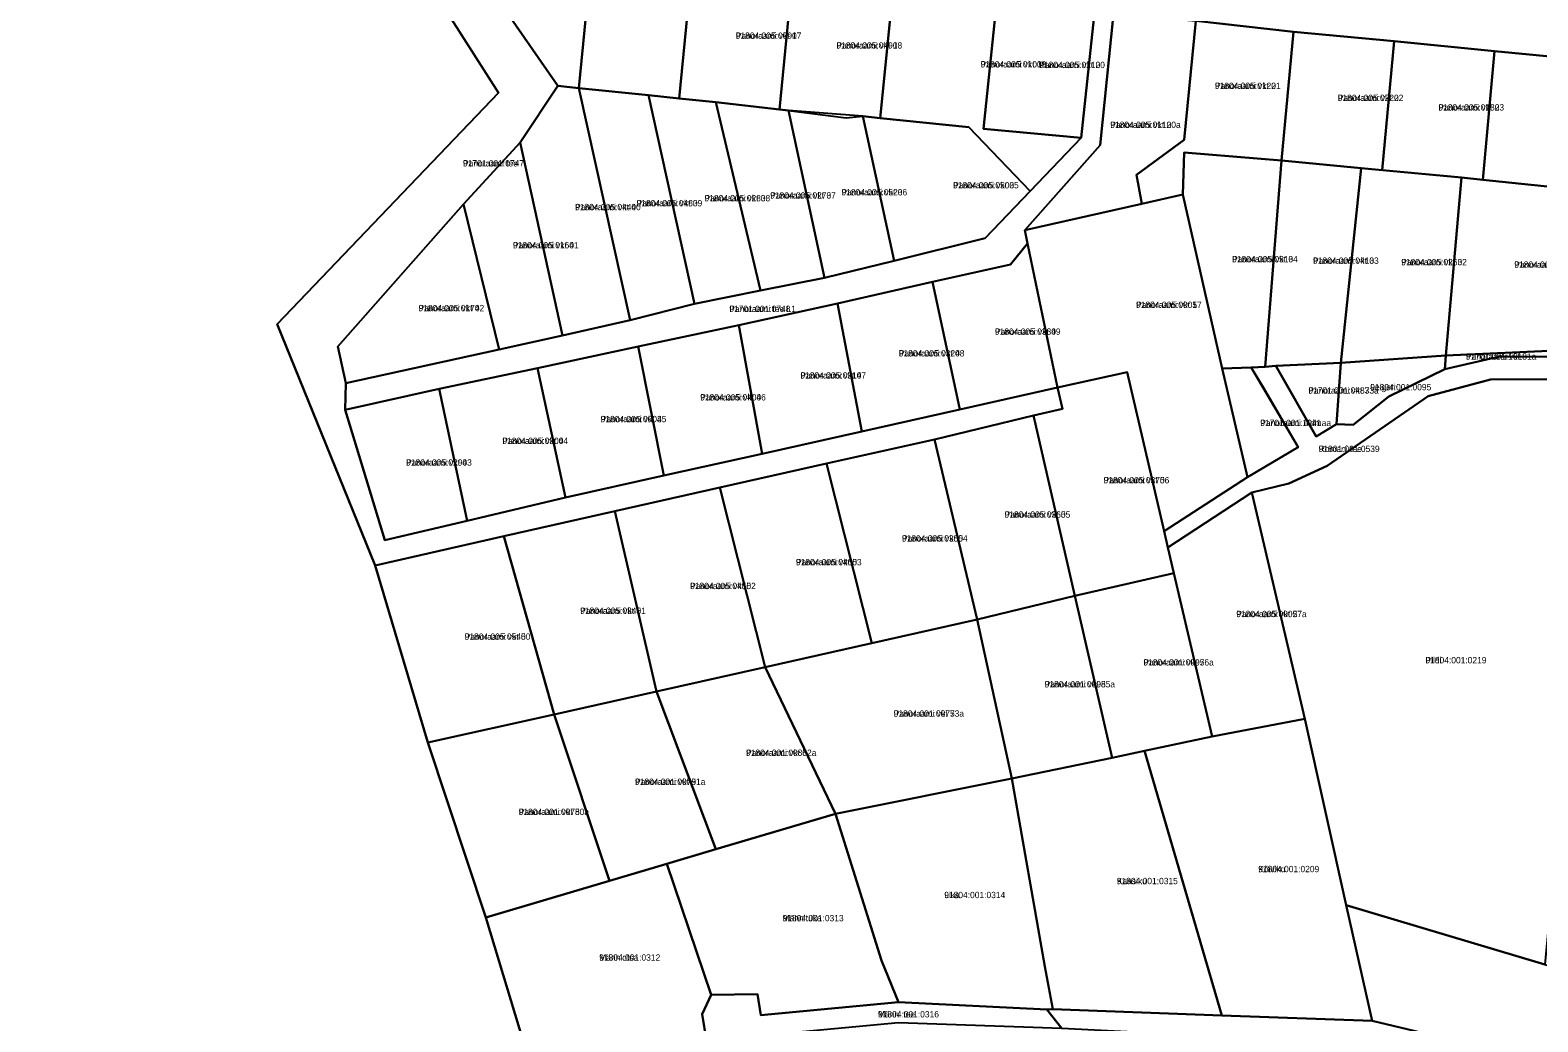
# Model space of a CAD drawing. Extents: x 655954 to 711923, y 6395079 to 6429745.
# Drawn here: x 676838.5 to 677196.9, y 6413488.9 to 6413724.6 of the extents above; entities that cross this region are included whole.
import ezdxf

# ---------------------------------------------------------------- set-up
doc = ezdxf.new("R2010")
doc.units = 0
for name, color, linetype in [('L_AADRESS', 7, 'Continuous'), ('PIIR', 7, 'Continuous'), ('TUNNUS', 7, 'Continuous')]:
    doc.layers.add(name, color=color, linetype=linetype)

msp = doc.modelspace()

# ---------------------------------------------------------------- linework, layer by layer
at = {"layer": 'PIIR'}
for points in [[(676722.83, 6413814.18), (676900.55, 6413787.01), (676949.83, 6413709.71), (676897.23, 6413654.7), (676920.56, 6413597.36), (676933.05, 6413555.27), (676946.82, 6413513.73), (676956.91, 6413480.43), (677002.62, 6413329.06), (677066.33, 6413319.15), (677231.27, 6413342.1), (677307.23, 6413354.1), (677309.72, 6413343.84), (677384.24, 6413366.61), (677380.25, 6413324.84), (677459.83, 6413354.2), (677597.5, 6413335.31), (677731.86, 6413311.49), (678085.04, 6413297.98), (678099.28, 6413215.93), (678143.84, 6412925.74)], [(676940.74, 6413744.84), (676963.98, 6413711.35), (676955.01, 6413697.89), (676941.57, 6413683.21), (676911.65, 6413649.44), (676913.57, 6413640.66), (676913.44, 6413634.36), (676922.88, 6413603.4), (676942.38, 6413608.01), (676965.79, 6413613.5), (676989.16, 6413618.75), (677012.51, 6413623.89), (677036.26, 6413629.17), (677059.56, 6413634.44), (677082.73, 6413639.64), (677083.95, 6413634.6), (677077.02, 6413633.03), (677053.51, 6413627.34), (677027.86, 6413621.6), (677002.51, 6413615.89), (676977.55, 6413610.28), (676951.13, 6413604.32), (676920.56, 6413597.36), (676897.23, 6413654.7), (676949.83, 6413709.71), (676900.55, 6413787.01)], [(677210.51, 6413717.3), (677186.62, 6413719.58), (677162.73, 6413721.93), (677138.84, 6413724.17), (677115.64, 6413726.84)], [(677204.22, 6413641.61), (677185.64, 6413641.55), (677170.88, 6413637.64), (677146.87, 6413621.01), (677137.72, 6413616.82), (677128.9, 6413614.75), (677108.98, 6413601.65), (677108.09, 6413605.56), (677127.88, 6413618.37), (677139.96, 6413625.52), (677128.81, 6413644.41), (677132.06, 6413644.54), (677134.66, 6413644.84), (677144.2, 6413628.03), (677149.07, 6413630.93), (677152.98, 6413630.76), (677161.51, 6413637.51), (677174.78, 6413644.05), (677187.89, 6413647.01), (677203.04, 6413646.92)]]:
    msp.add_lwpolyline(points, dxfattribs=at)
for points in [[(676963.98, 6413711.35), (676940.74, 6413744.84), (676971.97, 6413741.71), (676968.95, 6413710.82)], [(676968.95, 6413710.82), (676971.97, 6413741.71), (676995.85, 6413739.2), (676992.82, 6413708.35), (676985.56, 6413709.1)], [(676995.85, 6413739.2), (677019.7, 6413736.8), (677016.69, 6413705.72), (677001.51, 6413707.46), (676992.82, 6413708.35)], [(677040.59, 6413703.7), (677036.44, 6413704.17), (677018.82, 6413705.46), (677016.69, 6413705.72), (677019.7, 6413736.8), (677043.7, 6413734.54)], [(677043.7, 6413734.54), (677068.41, 6413732.49), (677065.16, 6413701.16), (677088.34, 6413698.99), (677076.26, 6413686.33), (677061.68, 6413701.52), (677040.59, 6413703.7)], [(677068.41, 6413732.49), (677091.65, 6413729.52), (677088.34, 6413698.99), (677065.16, 6413701.16)], [(677096.04, 6413728.43), (677092.88, 6413697.28), (677074.94, 6413677.09), (677075.6, 6413673.91), (677071.54, 6413668.9), (677053, 6413664.75), (677030.45, 6413659.62), (677007.01, 6413654.46), (676983.1, 6413649.39), (676959.15, 6413644.23), (676935.79, 6413639.38), (676913.44, 6413634.36), (676913.57, 6413640.66), (676950.06, 6413648.7), (676965.05, 6413651.99), (676981.14, 6413655.65), (676996.43, 6413659.58), (677012.12, 6413662.7), (677027.37, 6413665.74), (677043.95, 6413669.78), (677065.56, 6413675.12), (677076.26, 6413686.33), (677088.34, 6413698.99), (677091.65, 6413729.52)], [(677092.88, 6413697.28), (677096.04, 6413728.43), (677115.64, 6413726.84), (677112.86, 6413698.56), (677101.48, 6413690.21), (677102.75, 6413683.33), (677074.94, 6413677.09)], [(677112.88, 6413695.51), (677112.51, 6413685.52), (677102.75, 6413683.33), (677101.48, 6413690.21), (677112.86, 6413698.56), (677115.64, 6413726.84), (677138.84, 6413724.17), (677135.97, 6413693.58)], [(677135.97, 6413693.58), (677138.84, 6413724.17), (677162.73, 6413721.93), (677159.94, 6413691.32), (677154.89, 6413691.79)], [(677178.79, 6413689.57), (677159.94, 6413691.32), (677162.73, 6413721.93), (677186.62, 6413719.58), (677183.86, 6413689.04)], [(677207.63, 6413686.54), (677183.86, 6413689.04), (677186.62, 6413719.58), (677210.51, 6413717.3)], [(676955.01, 6413697.89), (676963.98, 6413711.35), (676968.95, 6413710.82), (676981.14, 6413655.65), (676965.05, 6413651.99)], [(676968.95, 6413710.82), (676985.56, 6413709.1), (676996.43, 6413659.58), (676981.14, 6413655.65)], [(676985.56, 6413709.1), (676992.82, 6413708.35), (677001.51, 6413707.46), (677012.12, 6413662.7), (676996.43, 6413659.58)], [(677012.12, 6413662.7), (677001.51, 6413707.46), (677016.69, 6413705.72), (677018.82, 6413705.46), (677027.37, 6413665.74)], [(677032.51, 6413703.76), (677036.44, 6413704.17), (677043.95, 6413669.78), (677027.37, 6413665.74), (677018.82, 6413705.46)], [(677043.95, 6413669.78), (677036.44, 6413704.17), (677040.59, 6413703.7), (677061.68, 6413701.52), (677076.26, 6413686.33), (677065.56, 6413675.12)], [(676950.06, 6413648.7), (676941.57, 6413683.21), (676955.01, 6413697.89), (676965.05, 6413651.99)], [(677132.06, 6413644.54), (677128.81, 6413644.41), (677121.89, 6413644.18), (677112.51, 6413685.52), (677112.88, 6413695.51), (677135.97, 6413693.58)], [(677154.89, 6413691.79), (677150.08, 6413645.55), (677134.66, 6413644.84), (677132.06, 6413644.54), (677135.97, 6413693.58)], [(677154.89, 6413691.79), (677178.79, 6413689.57), (677175.01, 6413647.24), (677150.08, 6413645.55)], [(677178.79, 6413689.57), (677183.86, 6413689.04), (677207.63, 6413686.54), (677203.2, 6413648.53), (677175.01, 6413647.24)], [(676913.57, 6413640.66), (676911.65, 6413649.44), (676941.57, 6413683.21), (676950.06, 6413648.7)], [(677112.51, 6413685.52), (677121.89, 6413644.18), (677127.88, 6413618.37), (677108.09, 6413605.56), (677099.27, 6413643.29), (677082.73, 6413639.64), (677075.6, 6413673.91), (677074.94, 6413677.09), (677102.75, 6413683.33)], [(677059.56, 6413634.44), (677053, 6413664.75), (677071.54, 6413668.9), (677075.6, 6413673.91), (677082.73, 6413639.64)], [(677059.56, 6413634.44), (677036.26, 6413629.17), (677030.45, 6413659.62), (677053, 6413664.75)], [(677036.26, 6413629.17), (677012.51, 6413623.89), (677007.01, 6413654.46), (677030.45, 6413659.62)], [(677012.51, 6413623.89), (676989.16, 6413618.75), (676983.1, 6413649.39), (677007.01, 6413654.46)], [(676965.79, 6413613.5), (676959.15, 6413644.23), (676983.1, 6413649.39), (676989.16, 6413618.75)], [(677149.07, 6413630.93), (677150.08, 6413645.55), (677175.01, 6413647.24), (677174.78, 6413644.05), (677161.51, 6413637.51), (677152.98, 6413630.76)], [(677187.89, 6413647.01), (677174.78, 6413644.05), (677175.01, 6413647.24), (677203.2, 6413648.53), (677203.04, 6413646.92)], [(676942.38, 6413608.01), (676935.79, 6413639.38), (676959.15, 6413644.23), (676965.79, 6413613.5)], [(677099.27, 6413643.29), (677108.09, 6413605.56), (677108.98, 6413601.65), (677110.38, 6413595.57), (677086.82, 6413590.14), (677077.02, 6413633.03), (677083.95, 6413634.6), (677082.73, 6413639.64)], [(677139.96, 6413625.52), (677127.88, 6413618.37), (677121.89, 6413644.18), (677128.81, 6413644.41), (677131.35, 6413640.1)], [(677144.2, 6413628.03), (677134.66, 6413644.84), (677150.08, 6413645.55), (677149.07, 6413630.93)], [(676913.44, 6413634.36), (676935.79, 6413639.38), (676942.38, 6413608.01), (676922.88, 6413603.4)], [(677128.9, 6413614.75), (677137.72, 6413616.82), (677146.87, 6413621.01), (677170.88, 6413637.64), (677185.64, 6413641.55), (677204.22, 6413641.61), (677211.49, 6413638.78), (677198.6, 6413502.57), (677151.34, 6413516.67), (677141.49, 6413560.95)], [(677063.67, 6413584.52), (677053.51, 6413627.34), (677077.02, 6413633.03), (677086.82, 6413590.14)], [(677038.64, 6413578.92), (677027.86, 6413621.6), (677053.51, 6413627.34), (677063.67, 6413584.52)], [(677013.27, 6413573.23), (677002.51, 6413615.89), (677027.86, 6413621.6), (677038.64, 6413578.92)], [(677013.27, 6413573.23), (676987.43, 6413567.4), (676977.55, 6413610.28), (677002.51, 6413615.89)], [(677128.9, 6413614.75), (677141.49, 6413560.95), (677119.5, 6413556.75), (677110.38, 6413595.57), (677108.98, 6413601.65)], [(676987.43, 6413567.4), (676963.1, 6413561.94), (676951.13, 6413604.32), (676977.55, 6413610.28)], [(676963.1, 6413561.94), (676933.05, 6413555.27), (676920.56, 6413597.36), (676951.13, 6413604.32)], [(677086.82, 6413590.14), (677110.38, 6413595.57), (677119.5, 6413556.75), (677103.38, 6413553.34), (677095.71, 6413551.68)], [(677086.82, 6413590.14), (677095.71, 6413551.68), (677071.85, 6413546.76), (677063.67, 6413584.52)], [(677063.67, 6413584.52), (677071.85, 6413546.76), (677030, 6413538.34), (677013.27, 6413573.23), (677038.64, 6413578.92)], [(677013.27, 6413573.23), (677030, 6413538.34), (677001.53, 6413529.92), (676987.43, 6413567.4)], [(676987.43, 6413567.4), (677001.53, 6413529.92), (676989.89, 6413526.46), (676976.29, 6413522.42), (676963.1, 6413561.94)], [(676963.1, 6413561.94), (676976.29, 6413522.42), (676946.82, 6413513.73), (676933.05, 6413555.27)], [(677103.38, 6413553.34), (677119.5, 6413556.75), (677141.49, 6413560.95), (677151.34, 6413516.67), (677157.51, 6413489.18), (677121.82, 6413490.43)], [(677071.85, 6413546.76), (677095.71, 6413551.68), (677103.38, 6413553.34), (677121.82, 6413490.43), (677081.65, 6413491.89), (677079.74, 6413502.08)], [(677030, 6413538.34), (677071.85, 6413546.76), (677079.74, 6413502.08), (677081.65, 6413491.89), (677080.22, 6413491.88), (677044.94, 6413493.61), (677040.88, 6413503.53)], [(676989.89, 6413526.46), (677001.53, 6413529.92), (677030, 6413538.34), (677040.88, 6413503.53), (677044.94, 6413493.61), (677012.26, 6413490.53), (677011.41, 6413495.5), (677000.44, 6413495.3)], [(677332.5, 6413536.88), (677338.79, 6413525.55), (677342.28, 6413516.7), (677349.03, 6413493.33), (677350.52, 6413489.54), (677337.82, 6413480.42), (677317.74, 6413472.95), (677288.46, 6413465.7), (677285.56, 6413465.3), (677276.11, 6413465.46), (677252.03, 6413468.89), (677204.37, 6413479.13), (677189.8, 6413481.47), (677157.51, 6413489.18), (677151.34, 6413516.67), (677198.6, 6413502.57), (677231.99, 6413492.6), (677272.8, 6413510.64)], [(676946.82, 6413513.73), (676976.29, 6413522.42), (676989.89, 6413526.46), (677000.44, 6413495.3), (676998.27, 6413490.74), (676999.3, 6413484.43), (676956.91, 6413480.43)], [(677000.44, 6413495.3), (677011.41, 6413495.5), (677012.26, 6413490.53), (677044.94, 6413493.61), (677080.22, 6413491.88), (677083.78, 6413487.37), (677044.94, 6413488.65), (676999.3, 6413484.43), (676998.27, 6413490.74)], [(677083.78, 6413487.37), (677080.22, 6413491.88), (677081.65, 6413491.89), (677121.82, 6413490.43), (677157.51, 6413489.18), (677189.8, 6413481.47), (677204.37, 6413479.13), (677252.03, 6413468.89), (677276.11, 6413465.46), (677285.56, 6413465.3), (677288.46, 6413465.7), (677317.74, 6413472.95), (677337.82, 6413480.42), (677350.52, 6413489.54), (677353.31, 6413480.81), (677291.42, 6413461.29), (677284.13, 6413460.03), (677272.97, 6413460.6), (677231.21, 6413468.51), (677155.12, 6413483.7)]]:
    msp.add_lwpolyline(points, close=True, dxfattribs=at)

# ---------------------------------------------------------------- texts
at = {"layer": 'L_AADRESS'}
for s, p in [('Panoraami vkt 17', (677006.26, 6413722.53)), ('Panoraami vkt 18', (677030.2, 6413720.22)), ('Panoraami vkt 19', (677064.47, 6413715.72)), ('Panoraami vkt 20', (677078.4, 6413715.57)), ('Panoraami vkt 21', (677120.16, 6413710.61)), ('Panoraami vkt 22', (677149.35, 6413707.75)), ('Panoraami vkt 23', (677173.28, 6413705.49)), ('Panoraami vkt 20a', (677095.29, 6413701.35)), ('Panoraami tee', (676941.43, 6413692.19)), ('Panoraami vkt 37', (677014.44, 6413684.57)), ('Panoraami vkt 36', (677031.39, 6413685.31)), ('Panoraami vkt 35', (677057.92, 6413686.98)), ('Panoraami vkt 40', (676968.07, 6413681.8)), ('Panoraami vkt 39', (676982.69, 6413682.72)), ('Panoraami vkt 38', (676998.84, 6413683.9)), ('Panoraami vkt 41', (676953.31, 6413672.72)), ('Panoraami vkt 34', (677124.24, 6413669.41)), ('Panoraami vkt 33', (677143.48, 6413669.06)), ('Panoraami vkt 32', (677164.43, 6413668.71)), ('Panoraami vkt 31', (677191.32, 6413668.12)), ('Panoraami vkt 42', (676930.86, 6413657.79)), ('Panoraami tee L1', (677004.74, 6413657.61)), ('Panoraami vkt 57', (677101.41, 6413658.58)), ('Panoraami vkt 49', (677067.86, 6413652.19)), ('Panoraami vkt 48', (677045.01, 6413647.04)), ('Panoraami vkt 31a', (677179.82, 6413646.29)), ('Panoraami vkt 47', (677021.63, 6413641.8)), ('Panoraami vkt 33a', (677142.37, 6413638.22)), ('Leigeri', (677157.08, 6413639)), ('Panoraami vkt 46', (676997.8, 6413636.58)), ('Panoraami vkt 45', (676974.15, 6413631.42)), ('Panoraami üldmaa', (677130.93, 6413630.5)), ('Panoraami vkt 44', (676950.79, 6413626.24)), ('Romani tee', (677144.81, 6413624.33)), ('Panoraami vkt 43', (676927.91, 6413621.1)), ('Panoraami vkt 56', (677093.7, 6413616.89)), ('Panoraami vkt 55', (677070.16, 6413608.73)), ('Panoraami vkt 54', (677045.77, 6413603.06)), ('Panoraami vkt 53', (677020.57, 6413597.41)), ('Panoraami vkt 52', (676995.41, 6413591.75)), ('Panoraami vkt 51', (676969.28, 6413585.87)), ('Panoraami vkt 57a', (677125.23, 6413585.09)), ('Panoraami vkt 50', (676941.83, 6413579.71)), ('Panoraami vkt 56a', (677103.16, 6413573.6)), ('Pildi', (677170.2, 6413574.11)), ('Panoraami vkt 55a', (677079.69, 6413568.39)), ('Panoraami vkt 53a', (677043.8, 6413561.43)), ('Panoraami vkt 52a', (677008.71, 6413552.12)), ('Panoraami vkt 51a', (676982.32, 6413545.23)), ('Panoraami vkt 50a', (676954.67, 6413538.06)), ('Kõiviku', (677130.45, 6413524.48)), ('Kaasiku', (677096.84, 6413521.63)), ('Lika', (677055.82, 6413518.31)), ('Männituka', (677017.41, 6413512.82)), ('Männiotsa', (676973.81, 6413503.45)), ('Männi tee', (677040.06, 6413489.96))]:
    msp.add_text(s, height=1.5, dxfattribs=at).set_placement(p)
at = {"layer": 'TUNNUS'}
for s, p in [('91804:005:0090', (677006.26, 6413722.53)), ('91804:005:0490', (677030.2, 6413720.22)), ('91804:005:0100', (677064.47, 6413715.72)), ('91804:005:0210', (677078.4, 6413715.57)), ('91804:005:0120', (677120.16, 6413710.61)), ('91804:005:0220', (677149.35, 6413707.75)), ('91804:005:0130', (677173.28, 6413705.49)), ('91804:005:0110', (677095.29, 6413701.35)), ('91701:001:0747', (676941.43, 6413692.19)), ('91804:005:0270', (677014.44, 6413684.57)), ('91804:005:0520', (677031.39, 6413685.31)), ('91804:005:0500', (677057.92, 6413686.98)), ('91804:005:0440', (676968.07, 6413681.8)), ('91804:005:0480', (676982.69, 6413682.72)), ('91804:005:0280', (676998.84, 6413683.9)), ('91804:005:0160', (676953.31, 6413672.72)), ('91804:005:0510', (677124.24, 6413669.41)), ('91804:005:0410', (677143.48, 6413669.06)), ('91804:005:0260', (677164.43, 6413668.71)), ('91804:005:0390', (677191.32, 6413668.12)), ('91804:005:0170', (676930.86, 6413657.79)), ('91701:001:0748', (677004.74, 6413657.61)), ('91804:005:0001', (677101.41, 6413658.58)), ('91804:005:0330', (677067.86, 6413652.19)), ('91804:005:0320', (677045.01, 6413647.04)), ('91701:001:1618', (677179.82, 6413646.29)), ('91804:005:0310', (677021.63, 6413641.8)), ('91701:001:0487', (677142.37, 6413638.22)), ('91804:001:0095', (677157.08, 6413639)), ('91804:005:0400', (676997.8, 6413636.58)), ('91804:005:0003', (676974.15, 6413631.42)), ('91701:001:1041', (677130.93, 6413630.5)), ('91804:005:0300', (676950.79, 6413626.24)), ('91801:001:0539', (677144.81, 6413624.33)), ('91804:005:0290', (676927.91, 6413621.1)), ('91804:005:0370', (677093.7, 6413616.89)), ('91804:005:0360', (677070.16, 6413608.73)), ('91804:005:0350', (677045.77, 6413603.06)), ('91804:005:0460', (677020.57, 6413597.41)), ('91804:005:0450', (676995.41, 6413591.75)), ('91804:005:0340', (676969.28, 6413585.87)), ('91804:005:0002', (677125.23, 6413585.09)), ('91804:005:0540', (676941.83, 6413579.71)), ('91804:001:0097', (677103.16, 6413573.6)), ('91804:001:0219', (677170.2, 6413574.11)), ('91804:001:0098', (677079.69, 6413568.39)), ('91804:001:0077', (677043.8, 6413561.43)), ('91804:001:0080', (677008.71, 6413552.12)), ('91804:001:0079', (676982.32, 6413545.23)), ('91804:001:0078', (676954.67, 6413538.06)), ('91804:001:0209', (677130.45, 6413524.48)), ('91804:001:0315', (677096.84, 6413521.63)), ('91804:001:0314', (677055.82, 6413518.31)), ('91804:001:0313', (677017.41, 6413512.82)), ('91804:001:0312', (676973.81, 6413503.45)), ('91804:001:0316', (677040.06, 6413489.96))]:
    msp.add_text(s, height=1.5, dxfattribs=at).set_placement(p)

doc.saveas('drawing.dxf')
